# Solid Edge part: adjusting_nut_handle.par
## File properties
Title: Adjusting nut handle
Author: Abhinav Rai
Template: Normal.par
Last saved by: Cadcim
Revision: 5
Application: Solid Edge
Material: aluminum
Accuracy: 0.99
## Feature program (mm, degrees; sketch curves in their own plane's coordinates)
sketch for "unnamed Protrusion 1" plane through (0, 0, 0) normal (0, -1, 0) x-axis (1, 0, 0)
  circle centre (0, 0) radius 9.5123
extrude "unnamed Protrusion 1" add finite 127 symmetric
chamfer "Chamfer_1" setback 1.5748
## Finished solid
Body 1: solid body, 5 faces, 4 edges, 0 vertices.
  Faces by surface: cone 2, plane 2, cylinder 1
  Edges by curve: circle 4
Bounding box of the edges (mm): 19.025 x 127.000 x 19.025, from (-9.5123, -63.5, -9.5123) to (9.5123, 63.5, 9.5123).
Cylindrical faces by radius (mm): R9.5123 x1
Conical faces (half-angle, radius in mm at the cone's reference point): 45 deg R7.9375 x1, 45 deg R9.5123 x1
Planar faces by outward normal: +y 1, -y 1
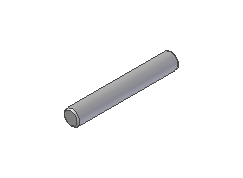
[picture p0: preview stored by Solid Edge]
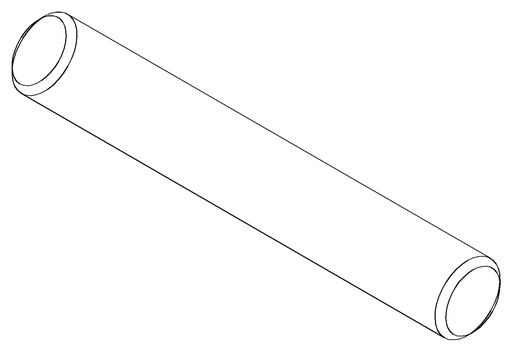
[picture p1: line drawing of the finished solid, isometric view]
